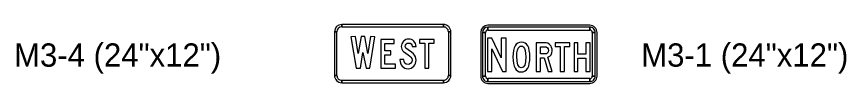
# Model space of a CAD drawing. Extents: x 620856.8 to 620948.6, y 415598.8 to 415658.2.
# Drawn here: x 620933.17 to 620947.43, y 415644.36 to 415645.38 of the extents above; entities that cross this region are included whole.
import ezdxf

# ---------------------------------------------------------------- set-up
doc = ezdxf.new("R2010")
doc.units = 0
doc.layers.add('SIGNS', color=7, linetype='Continuous')

msp = doc.modelspace()

# ---------------------------------------------------------------- linework, layer by layer
at = {"layer": 'SIGNS'}
for p, q in [((620938.755, 415645.335), (620938.755, 415645.377)), ((620940.505, 415645.377), (620940.505, 415645.335)), ((620943.018, 415645.365), (620941.268, 415645.365)), ((620938.63, 415645.252), (620938.672, 415645.252)), ((620940.588, 415645.252), (620940.63, 415645.252)), ((620941.143, 415645.24), (620941.143, 415644.49)), ((620941.175, 415645.24), (620941.227, 415645.24)), ((620941.268, 415645.281), (620941.268, 415645.333)), ((620943.018, 415645.333), (620943.018, 415645.281)), ((620943.06, 415645.24), (620943.112, 415645.24)), ((620943.143, 415644.49), (620943.143, 415645.24)), ((620938.672, 415644.502), (620938.63, 415644.502)), ((620940.63, 415644.502), (620940.588, 415644.502)), ((620938.755, 415644.377), (620938.755, 415644.418)), ((620940.505, 415644.418), (620940.505, 415644.377)), ((620941.227, 415644.49), (620941.175, 415644.49)), ((620941.268, 415644.396), (620941.268, 415644.448)), ((620941.268, 415644.365), (620943.018, 415644.365)), ((620943.018, 415644.448), (620943.018, 415644.396)), ((620943.112, 415644.49), (620943.06, 415644.49))]:
    msp.add_line(p, q, dxfattribs=at)
for points in [[(620940.505, 415645.377), (620938.755, 415645.377), (620938.755, 415645.335), (620940.505, 415645.335), (620940.505, 415645.377), (620940.505, 415645.377)], [(620938.63, 415645.252), (620938.63, 415644.502), (620938.672, 415644.502), (620938.672, 415645.252), (620938.63, 415645.252), (620938.63, 415645.252)], [(620940.63, 415644.502), (620940.63, 415645.252), (620940.588, 415645.252), (620940.588, 415644.502), (620940.63, 415644.502), (620940.63, 415644.502)], [(620941.175, 415645.24), (620941.175, 415644.49), (620941.227, 415644.49), (620941.227, 415645.24), (620941.175, 415645.24), (620941.175, 415645.24)], [(620943.018, 415645.333), (620941.268, 415645.333), (620941.268, 415645.281), (620943.018, 415645.281), (620943.018, 415645.333), (620943.018, 415645.333)], [(620943.112, 415644.49), (620943.112, 415645.24), (620943.06, 415645.24), (620943.06, 415644.49), (620943.112, 415644.49), (620943.112, 415644.49)], [(620939.003, 415644.627), (620939.075, 415644.627), (620939.119, 415644.896), (620939.172, 415644.627), (620939.239, 415644.627), (620939.326, 415645.166), (620939.25, 415645.171), (620939.202, 415644.881), (620939.15, 415645.171), (620939.089, 415645.171), (620939.036, 415644.881), (620938.99, 415645.171), (620938.913, 415645.166)], [(620939.676, 415644.694), (620939.496, 415644.694), (620939.496, 415644.858), (620939.598, 415644.858), (620939.598, 415644.925), (620939.496, 415644.925), (620939.496, 415645.05), (620939.658, 415645.05), (620939.658, 415645.117), (620939.424, 415645.117), (620939.424, 415644.627), (620939.676, 415644.627)], [(620939.755, 415644.774), (620939.755, 415644.77), (620939.757, 415644.74), (620939.764, 415644.712), (620939.776, 415644.687), (620939.793, 415644.664), (620939.814, 415644.643), (620939.838, 415644.629), (620939.865, 415644.62), (620939.894, 415644.617), (620939.923, 415644.62), (620939.95, 415644.628), (620939.973, 415644.642), (620939.994, 415644.662), (620940.011, 415644.685), (620940.023, 415644.71), (620940.03, 415644.737), (620940.032, 415644.767), (620940.029, 415644.795), (620940.021, 415644.822), (620940.007, 415644.848), (620939.988, 415644.872), (620939.951, 415644.904), (620939.894, 415644.943), (620939.856, 415644.971), (620939.848, 415644.986), (620939.846, 415645.002), (620939.85, 415645.024), (620939.863, 415645.042), (620939.882, 415645.055), (620939.905, 415645.059), (620939.929, 415645.055), (620939.947, 415645.043), (620939.957, 415645.027), (620939.964, 415645.002), (620940.032, 415645.002), (620940.021, 415645.052), (620939.995, 415645.091), (620939.976, 415645.107), (620939.954, 415645.118), (620939.93, 415645.125), (620939.903, 415645.127), (620939.878, 415645.124), (620939.855, 415645.117), (620939.834, 415645.105), (620939.814, 415645.089), (620939.787, 415645.048), (620939.777, 415645), (620939.78, 415644.975), (620939.787, 415644.953), (620939.798, 415644.932), (620939.815, 415644.913), (620939.895, 415644.856), (620939.924, 415644.834), (620939.942, 415644.817), (620939.959, 415644.792), (620939.964, 415644.766), (620939.959, 415644.737), (620939.945, 415644.713), (620939.922, 415644.695), (620939.894, 415644.689), (620939.864, 415644.695), (620939.841, 415644.715), (620939.827, 415644.742), (620939.823, 415644.774)], [(620940.182, 415644.627), (620940.253, 415644.627), (620940.253, 415645.056), (620940.344, 415645.056), (620940.344, 415645.117), (620940.092, 415645.117), (620940.092, 415645.056), (620940.182, 415645.056)], [(620941.259, 415644.573), (620941.337, 415644.573), (620941.337, 415644.959), (620941.518, 415644.573), (620941.582, 415644.573), (620941.582, 415645.145), (620941.494, 415645.145), (620941.494, 415644.804), (620941.337, 415645.145), (620941.259, 415645.145)], [(620942.51, 415644.573), (620942.582, 415644.573), (620942.582, 415645.002), (620942.673, 415645.002), (620942.673, 415645.063), (620942.421, 415645.063), (620942.421, 415645.002), (620942.51, 415645.002)], [(620942.748, 415644.573), (620942.815, 415644.573), (620942.815, 415644.798), (620942.95, 415644.798), (620942.95, 415644.573), (620943.025, 415644.573), (620943.025, 415645.063), (620942.95, 415645.063), (620942.95, 415644.867), (620942.815, 415644.867), (620942.815, 415645.063), (620942.748, 415645.063)], [(620938.755, 415644.377), (620940.505, 415644.377), (620940.505, 415644.418), (620938.755, 415644.418), (620938.755, 415644.377), (620938.755, 415644.377)], [(620941.268, 415644.396), (620943.018, 415644.396), (620943.018, 415644.448), (620941.268, 415644.448), (620941.268, 415644.396), (620941.268, 415644.396)]]:
    msp.add_lwpolyline(points, close=True, dxfattribs=at)
for points in [[(620941.989, 415644.819), (620941.986, 415644.878), (620941.979, 415644.93), (620941.968, 415644.974), (620941.952, 415645.009), (620941.932, 415645.037), (620941.907, 415645.057), (620941.878, 415645.069), (620941.844, 415645.073), (620941.809, 415645.069), (620941.779, 415645.057), (620941.754, 415645.037), (620941.733, 415645.009), (620941.717, 415644.974), (620941.706, 415644.93), (620941.699, 415644.878), (620941.697, 415644.819), (620941.699, 415644.759), (620941.706, 415644.707), (620941.717, 415644.663), (620941.733, 415644.627), (620941.753, 415644.599), (620941.778, 415644.579), (620941.807, 415644.567), (620941.841, 415644.563), (620941.875, 415644.567), (620941.905, 415644.579), (620941.931, 415644.599), (620941.952, 415644.627), (620941.968, 415644.663), (620941.979, 415644.707), (620941.986, 415644.759), (620941.989, 415644.819)], [(620941.918, 415644.821), (620941.913, 415644.739), (620941.899, 415644.681), (620941.875, 415644.646), (620941.841, 415644.635), (620941.808, 415644.647), (620941.783, 415644.684), (620941.769, 415644.746), (620941.764, 415644.834), (620941.767, 415644.891), (620941.776, 415644.939), (620941.787, 415644.969), (620941.802, 415644.99), (620941.82, 415645.003), (620941.841, 415645.007), (620941.863, 415645.003), (620941.88, 415644.989), (620941.895, 415644.965), (620941.906, 415644.933), (620941.915, 415644.882), (620941.918, 415644.821)], [(620942.095, 415644.573), (620942.172, 415644.573), (620942.172, 415644.806), (620942.237, 415644.806), (620942.301, 415644.573), (620942.371, 415644.573), (620942.3, 415644.815), (620942.331, 415644.832), (620942.354, 415644.859), (620942.367, 415644.89), (620942.371, 415644.926), (620942.369, 415644.956), (620942.363, 415644.982), (620942.353, 415645.005), (620942.338, 415645.025), (620942.319, 415645.042), (620942.297, 415645.054), (620942.271, 415645.061), (620942.241, 415645.063), (620942.095, 415645.063), (620942.095, 415644.573)], [(620942.172, 415644.871), (620942.172, 415644.996), (620942.243, 415644.996), (620942.269, 415644.992), (620942.289, 415644.979), (620942.302, 415644.959), (620942.306, 415644.933), (620942.302, 415644.906), (620942.291, 415644.887), (620942.272, 415644.875), (620942.246, 415644.871), (620942.172, 415644.871)]]:
    msp.add_lwpolyline(points, dxfattribs=at)
for centre, radius, start, end in [((620938.755, 415645.252), 0.125, 90.0002, 179.9998), ((620940.505, 415645.252), 0.125, 0, 90.0002), ((620941.268, 415645.24), 0.125, 90.0002, 179.9998), ((620943.018, 415645.24), 0.125, 360, 90.0002), ((620938.755, 415645.252), 0.0833, 90.0002, 179.9998), ((620940.505, 415645.252), 0.0833, 0, 90.0002), ((620941.268, 415645.24), 0.0937, 90.0002, 179.9998), ((620941.268, 415645.24), 0.0417, 90.0002, 179.9998), ((620943.018, 415645.24), 0.0937, 360, 90.0002), ((620943.018, 415645.24), 0.0417, 360, 90.0002), ((620938.755, 415644.502), 0.125, 179.9998, 270.0001), ((620938.755, 415644.502), 0.0833, 179.9998, 270.0001), ((620940.505, 415644.502), 0.125, 270.0001, 0.0003), ((620940.505, 415644.502), 0.0833, 270.0001, 0.0003), ((620941.268, 415644.49), 0.125, 179.9998, 270.0001), ((620941.268, 415644.49), 0.0937, 179.9998, 270.0001), ((620941.268, 415644.49), 0.0417, 179.9998, 270.0001), ((620943.018, 415644.49), 0.125, 270.0001, 0.0003), ((620943.018, 415644.49), 0.0937, 270.0001, 0.0003), ((620943.018, 415644.49), 0.0417, 270.0001, 0.0003)]:
    msp.add_arc(centre, radius, start, end, dxfattribs=at)

# ---------------------------------------------------------------- texts
for s, p in [('M3-4 (24"x12")', (620933.122, 415644.653)), ('M3-1 (24"x12")', (620943.902, 415644.653))]:
    msp.add_text(s, height=0.4, rotation=0, dxfattribs=at).set_placement(p)

doc.saveas('drawing.dxf')
